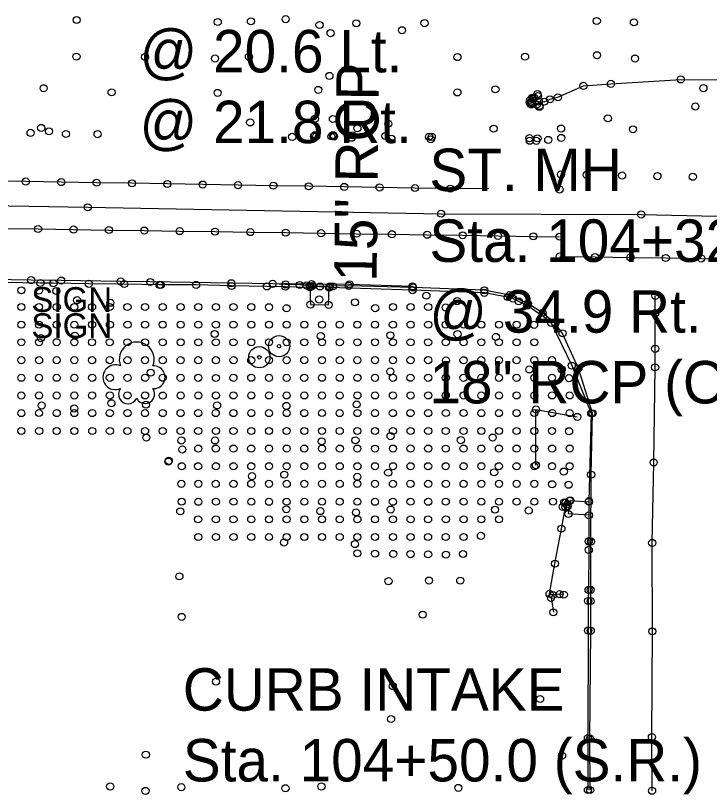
# Model space of a CAD drawing. Extents: x 20503438 to 20508873, y 7964251 to 7984667.
# Drawn here: x 20505361.4 to 20505557.5, y 7970387.9 to 7970607.9 of the extents above; entities that cross this region are included whole.
import ezdxf

# ---------------------------------------------------------------- set-up
doc = ezdxf.new("R2010")
doc.units = 0
for name, color, linetype in [('SurBreakLine', 7, 'Continuous'), ('SurBuilding', 7, 'Continuous'), ('SurConcreteSlab', 7, 'Continuous'), ('SurDrainageArrowDown', 7, 'Continuous'), ('SurDrainageArrowUp', 7, 'Continuous'), ('SurEdgeCurb', 7, 'Continuous'), ('SurEdgeRoadPaved', 7, 'Continuous'), ('SurFenceChainLink', 7, 'Continuous'), ('SurFenceWood', 7, 'Continuous'), ('SurNaturalCells', 7, 'Continuous'), ('SurPointsNonDTM', 7, 'Continuous'), ('SurRoadPoints', 7, 'Continuous'), ('SurSurveyPoints', 7, 'Continuous'), ('SurTxtDrainage', 7, 'Continuous')]:
    doc.layers.add(name, color=color, linetype=linetype)

msp = doc.modelspace()

# ---------------------------------------------------------------- linework, layer by layer
at = {"layer": 'SurBreakLine'}
for points in [[(20504771.9, 7970563.37), (20504797.86, 7970563), (20504843.99, 7970562.34), (20504867.04, 7970562.01), (20505027.11, 7970559.46), (20505056.57, 7970559.02), (20505122.33, 7970557.99), (20505134.3, 7970557.78), (20505181.34, 7970557.02), (20505190.04, 7970556.88), (20505298.19, 7970555.19), (20505381.79, 7970553.77), (20505481.65, 7970551.95), (20505538.21, 7970551.74), (20505602.69, 7970550.28), (20505659.98, 7970549.19), (20505725.91, 7970548.38)], [(20505541.3, 7970388.88), (20505541.24, 7970404.04), (20505541.37, 7970433.93), (20505541.32, 7970458.93), (20505541.74, 7970481.63), (20505542.15, 7970508.53), (20505542.17, 7970523.87), (20505542.2, 7970528.72)], [(20505517.44, 7970469.27), (20505517.44, 7970469.84), (20505516.88, 7970470.28), (20505516.46, 7970470.37), (20505516.05, 7970469.09)]]:
    msp.add_lwpolyline(points, dxfattribs=at)
at = {"layer": 'SurBuilding'}
msp.add_line((20505404.58, 7970481.91), (20505404.58, 7970481.91), dxfattribs=at)
at = {"layer": 'SurConcreteSlab'}
for points in [[(20505495.13, 7970558.96), (20505484.26, 7970559.04), (20505474.26, 7970559.2), (20505464.27, 7970559.37), (20505454.27, 7970559.53), (20505444.27, 7970559.7), (20505434.27, 7970559.86), (20505424.27, 7970560.02), (20505414.28, 7970560.19), (20505404.28, 7970560.36), (20505394.28, 7970560.54), (20505384.28, 7970560.71), (20505374.28, 7970560.88), (20505364.28, 7970561.05), (20505354.29, 7970561.22)], [(20505357.76, 7970547.78), (20505367.76, 7970547.64), (20505377.76, 7970547.49), (20505387.76, 7970547.34), (20505397.76, 7970547.19), (20505407.76, 7970547.04), (20505417.75, 7970546.89), (20505427.75, 7970546.75), (20505437.75, 7970546.6), (20505447.75, 7970546.45), (20505457.75, 7970546.3), (20505467.75, 7970546.15), (20505477.74, 7970546), (20505487.74, 7970545.86), (20505497.74, 7970545.71), (20505507.74, 7970545.56), (20505515.13, 7970545.45)], [(20505515.18, 7970539.88), (20505525.17, 7970539.73), (20505535.17, 7970539.59), (20505545.17, 7970539.44), (20505555.17, 7970539.3), (20505565.17, 7970539.15), (20505575.17, 7970539.01), (20505585.16, 7970538.86), (20505595.16, 7970538.71), (20505605.16, 7970538.57), (20505615.16, 7970538.42), (20505625.16, 7970538.27), (20505635.16, 7970538.13), (20505645.16, 7970537.98), (20505655.15, 7970537.84), (20505665.15, 7970537.69), (20505675.15, 7970537.55), (20505685.15, 7970537.4), (20505695.15, 7970537.26), (20505705.15, 7970537.12), (20505715.14, 7970537)], [(20505506.07, 7970526.04), (20505510.46, 7970522.99), (20505512.8, 7970521.08), (20505518.59, 7970509.03), (20505524.09, 7970495.56), (20505523.45, 7970470.73), (20505523.39, 7970459.44), (20505523.37, 7970459.31)]]:
    msp.add_lwpolyline(points, dxfattribs=at)
for points in [[(20505444.59, 7970531.35), (20505444.73, 7970526.28), (20505449.86, 7970526.19), (20505450.05, 7970531.21)], [(20505517.64, 7970467.11), (20505518.14, 7970470.91), (20505523.43, 7970470.56), (20505523.42, 7970466.72)]]:
    msp.add_lwpolyline(points, close=True, dxfattribs=at)
at = {"layer": 'SurDrainageArrowDown'}
msp.add_lwpolyline([(20505516.34, 7970444.31), (20505515.13, 7970444.43), (20505513.26, 7970444.21), (20505512.31, 7970444.53), (20505513.84, 7970453.07), (20505515.67, 7970462.95), (20505516.82, 7970469.04)], dxfattribs=at)
at = {"layer": 'SurDrainageArrowUp'}
for points in [[(20505509.27, 7970583.65), (20505510.79, 7970583.61), (20505512.44, 7970584.29), (20505514.65, 7970584.86), (20505521.9, 7970588.08), (20505529.65, 7970588.65), (20505549.4, 7970589.9), (20505570.14, 7970589.83)], [(20505512.72, 7970443.37), (20505513.39, 7970439.31)]]:
    msp.add_lwpolyline(points, dxfattribs=at)
at = {"layer": 'SurEdgeCurb'}
for points in [[(20505444.6, 7970531.13), (20505437.65, 7970531.33), (20505432.42, 7970531.41), (20505422.42, 7970531.53), (20505412.42, 7970531.84), (20505402.42, 7970531.84), (20505402.08, 7970531.85), (20505392.08, 7970532.07), (20505382.08, 7970532.14), (20505372.08, 7970532.28), (20505368.42, 7970532.36), (20505358.42, 7970532.5)], [(20505455.52, 7970531.57), (20505451.07, 7970531.44), (20505450.19, 7970531.38), (20505447.43, 7970531.4), (20505445.14, 7970531.49), (20505444.57, 7970531.51), (20505443.66, 7970531.66), (20505441.7, 7970531.81), (20505437.7, 7970531.96), (20505434.06, 7970532.14)], [(20505506.07, 7970526.04), (20505505.93, 7970526.03), (20505503.6, 7970527.18), (20505501.97, 7970527.96), (20505500.46, 7970528.4), (20505493.88, 7970529.59), (20505473.59, 7970530.35), (20505450.04, 7970531.07)], [(20505523.78, 7970389.08), (20505523.74, 7970403.67), (20505523.95, 7970434.1), (20505523.93, 7970442.49), (20505523.93, 7970445.66), (20505524.02, 7970459.3), (20505524.07, 7970478.22), (20505524.47, 7970495.56), (20505520.47, 7970508.23), (20505515.98, 7970518.14), (20505513.93, 7970520.95), (20505510.35, 7970523.97), (20505506.16, 7970526.54), (20505501, 7970528.93), (20505493.87, 7970530.31), (20505473.72, 7970531.12), (20505455.52, 7970531.57)], [(20505523.37, 7970459.31), (20505523.39, 7970456.96), (20505523.34, 7970445.65), (20505523.22, 7970442.53), (20505523.22, 7970434.16), (20505523.15, 7970403.79), (20505523.15, 7970389.09)]]:
    msp.add_lwpolyline(points, dxfattribs=at)
at = {"layer": 'SurEdgeRoadPaved'}
msp.add_lwpolyline([(20505473.55, 7970531.4), (20505455.77, 7970531.96), (20505445.03, 7970532.04), (20505434.06, 7970532.14), (20505422.36, 7970532.31), (20505399.47, 7970532.66), (20505391.08, 7970532.79), (20505374.29, 7970533.06), (20505365.79, 7970533.19), (20505337.25, 7970533.63), (20505320.09, 7970533.9), (20505273.98, 7970534.71), (20505259.19, 7970535), (20505244.39, 7970535.28), (20505238.48, 7970535.4)], dxfattribs=at)
at = {"layer": 'SurFenceChainLink'}
msp.add_lwpolyline([(20505508.45, 7970480.87), (20505508.47, 7970496.65), (20505520.14, 7970494.53)], dxfattribs=at)
at = {"layer": 'SurFenceWood'}
msp.add_line((20505404.68, 7970482.13), (20505404.68, 7970482.13), dxfattribs=at)
at = {"layer": 'SurNaturalCells'}
for centre, radius, start, end in [((20505395.62, 7970510.77), 4.92, 338.2051, 201.7949), ((20505389.6, 7970505.74), 3.51, 65.4824, 294.5175), ((20505400.42, 7970505.74), 3.21, 265.9982, 94.0018), ((20505393.19, 7970500.92), 2.68, 142.7501, 335.3223), ((20505398.01, 7970501), 2.67, 206.5242, 35.4033)]:
    msp.add_arc(centre, radius, start, end, dxfattribs=at)
at = {"layer": 'SurPointsNonDTM'}
for centre in [(20505525.67, 7970606.42), (20505450.41, 7970602.98), (20505470.61, 7970603.8), (20505450.1, 7970590.89), (20505542.16, 7970513.77), (20505508.47, 7970496.65), (20505520.14, 7970494.53), (20505404.58, 7970481.91), (20505404.68, 7970482.13), (20505508.45, 7970480.87)]:
    msp.add_circle(centre, 1, dxfattribs=at)
at = {"layer": 'SurRoadPoints'}
for centre, radius in [((20505435.86, 7970514.52), 3), ((20505430.27, 7970511.39), 3), ((20505435.86, 7970514.52), 0.5), ((20505430.27, 7970511.39), 0.5)]:
    msp.add_circle(centre, radius, dxfattribs=at)
at = {"layer": 'SurSurveyPoints'}
for centre in [(20505378.64, 7970606.69), (20505437.73, 7970606.94), (20505418.53, 7970606.12), (20505427.9, 7970606.32), (20505447.29, 7970605.29), (20505457.7, 7970605.76), (20505476.97, 7970605.8), (20505536.15, 7970606.02), (20505378.6, 7970596.35), (20505397.97, 7970596.25), (20505417.76, 7970595.81), (20505427.33, 7970596.31), (20505486.27, 7970596.21), (20505505.4, 7970596.32), (20505525.73, 7970596.73), (20505536.46, 7970595.8), (20505549.4, 7970589.9), (20505369.31, 7970587.41), (20505446.94, 7970586.94), (20505497.02, 7970587.1), (20505521.9, 7970588.08), (20505529.65, 7970588.65), (20505555.8, 7970587.43), (20505388.52, 7970586.25), (20505418.49, 7970586.1), (20505486.27, 7970586.23), (20505507.44, 7970584.76), (20505507.98, 7970584.71), (20505508.88, 7970585.76), (20505509.02, 7970585.22), (20505514.65, 7970584.86), (20505506.74, 7970583.37), (20505506.83, 7970584.11), (20505507.07, 7970583.6), (20505507.09, 7970582.84), (20505507.38, 7970583.19), (20505507.5, 7970584.39), (20505508.69, 7970582.76), (20505509.27, 7970583.65), (20505509.48, 7970582.37), (20505510.79, 7970583.61), (20505512.44, 7970584.29), (20505509.45, 7970582.12), (20505553.53, 7970582.26), (20505445.99, 7970578.81), (20505451.08, 7970578.72), (20505528.79, 7970578.89), (20505368.62, 7970576.21), (20505427.7, 7970577.74), (20505458, 7970576.1), (20505466.74, 7970577.38), (20505496.49, 7970575.98), (20505515.58, 7970576.01), (20505515.58, 7970576.01), (20505535.9, 7970575.81), (20505365.62, 7970574.8), (20505370.84, 7970575.22), (20505375.61, 7970574.47), (20505384.56, 7970574.44), (20505439.56, 7970573.67), (20505445.77, 7970573.81), (20505445.98, 7970574.14), (20505445.98, 7970574.04), (20505446.4, 7970573.88), (20505450.65, 7970573.8), (20505451.09, 7970574.21), (20505451.09, 7970573.91), (20505451.4, 7970573.77), (20505455.28, 7970574.06), (20505456.57, 7970574.12), (20505465.9, 7970573.92), (20505478.27, 7970573.68), (20505479.02, 7970573.68), (20505456.35, 7970573.41), (20505467.61, 7970573.12), (20505478.75, 7970572.99), (20505506.63, 7970573.3), (20505506.7, 7970572.57), (20505508.57, 7970572.54), (20505508.9, 7970573.26), (20505511.94, 7970572.81), (20505515.61, 7970573.37), (20505515.54, 7970563.06), (20505522.81, 7970562.93), (20505532.81, 7970562.75), (20505542.8, 7970562.57), (20505364.28, 7970561.05), (20505374.28, 7970560.88), (20505384.28, 7970560.71), (20505394.28, 7970560.54), (20505404.28, 7970560.36), (20505552.8, 7970562.39), (20505414.28, 7970560.19), (20505424.27, 7970560.02), (20505434.27, 7970559.86), (20505444.27, 7970559.7), (20505454.27, 7970559.53), (20505464.27, 7970559.37), (20505474.26, 7970559.2), (20505484.26, 7970559.04), (20505515.12, 7970558.8), (20505381.79, 7970553.77), (20505481.65, 7970551.95), (20505538.21, 7970551.74), (20505367.76, 7970547.64), (20505377.76, 7970547.49), (20505387.76, 7970547.34), (20505397.76, 7970547.19), (20505407.76, 7970547.04), (20505417.75, 7970546.89), (20505427.75, 7970546.75), (20505437.75, 7970546.6), (20505447.75, 7970546.45), (20505457.75, 7970546.3), (20505467.75, 7970546.15), (20505477.74, 7970546), (20505487.74, 7970545.86), (20505497.74, 7970545.71), (20505507.74, 7970545.56), (20505515.13, 7970545.45), (20505515.18, 7970539.88), (20505525.17, 7970539.73), (20505535.17, 7970539.59), (20505545.17, 7970539.44), (20505555.17, 7970539.3), (20505365.79, 7970533.19), (20505368.42, 7970532.36), (20505372.08, 7970532.28), (20505374.29, 7970533.06), (20505382.08, 7970532.14), (20505391.08, 7970532.79), (20505392.08, 7970532.07), (20505399.47, 7970532.66), (20505402.08, 7970531.85), (20505402.42, 7970531.84), (20505412.42, 7970531.84), (20505422.36, 7970532.31), (20505434.06, 7970532.14), (20505437.7, 7970531.96), (20505441.7, 7970531.81), (20505445.03, 7970532.04), (20505455.77, 7970531.96), (20505363.01, 7970530.31), (20505367.97, 7970530.22), (20505372.89, 7970530.11), (20505422.42, 7970531.53), (20505432.42, 7970531.41), (20505437.65, 7970531.33), (20505443.66, 7970531.66), (20505444.57, 7970531.51), (20505444.59, 7970531.35), (20505444.6, 7970531.13), (20505445.14, 7970531.49), (20505447.43, 7970531.4), (20505450.05, 7970531.21), (20505450.04, 7970531.07), (20505450.19, 7970531.38), (20505451.07, 7970531.44), (20505455.52, 7970531.57), (20505455.52, 7970531.57), (20505473.55, 7970531.4), (20505473.59, 7970530.35), (20505473.72, 7970531.12), (20505493.87, 7970530.31), (20505493.88, 7970529.59), (20505378.78, 7970527.52), (20505447.2, 7970527.71), (20505477.51, 7970528.79), (20505500.46, 7970528.4), (20505501, 7970528.93), (20505501.97, 7970527.96), (20505542.2, 7970528.72), (20505363, 7970525.6), (20505368.02, 7970525.59), (20505373.02, 7970525.59), (20505377.99, 7970525.59), (20505383.01, 7970525.6), (20505388.02, 7970525.58), (20505388.16, 7970526.78), (20505393.01, 7970525.59), (20505398, 7970525.58), (20505402.98, 7970525.58), (20505408.02, 7970525.59), (20505413.01, 7970525.59), (20505418, 7970525.59), (20505422.97, 7970525.59), (20505427.99, 7970525.59), (20505433, 7970525.52), (20505437.98, 7970525.24), (20505444.73, 7970526.28), (20505449.86, 7970526.19), (20505457.34, 7970526.9), (20505463.02, 7970525.27), (20505468.04, 7970525.58), (20505473.02, 7970525.58), (20505478.01, 7970525.59), (20505482.95, 7970525.47), (20505486.22, 7970527.24), (20505503.6, 7970527.18), (20505505.93, 7970526.03), (20505506.07, 7970526.04), (20505506.16, 7970526.54), (20505510.35, 7970523.97), (20505510.46, 7970522.99), (20505542.17, 7970523.87), (20505512.8, 7970521.08), (20505513.93, 7970520.95), (20505363, 7970520.59), (20505368.02, 7970520.6), (20505373.01, 7970520.6), (20505377.98, 7970520.58), (20505383.01, 7970520.6), (20505388.04, 7970520.61), (20505393.02, 7970520.59), (20505397.99, 7970520.6), (20505402.97, 7970520.61), (20505408.03, 7970520.6), (20505413.01, 7970520.6), (20505417.99, 7970520.6), (20505422.97, 7970520.6), (20505428, 7970520.6), (20505433.01, 7970520.6), (20505438, 7970520.6), (20505442.99, 7970520.6), (20505448.01, 7970520.61), (20505453.01, 7970520.61), (20505457.99, 7970520.6), (20505462.98, 7970520.6), (20505468.02, 7970520.6), (20505473.03, 7970520.6), (20505478, 7970520.6), (20505482.98, 7970520.61), (20505488, 7970520.59), (20505493.02, 7970520.6), (20505498, 7970520.6), (20505503, 7970520.6), (20505507.94, 7970520.56), (20505368.54, 7970516.79), (20505378.15, 7970517.46), (20505417.65, 7970517.96), (20505447.66, 7970517.35), (20505467.29, 7970517.59), (20505486.3, 7970517.92), (20505497.15, 7970517.14), (20505515.98, 7970518.14), (20505363, 7970515.62), (20505368.02, 7970515.62), (20505373.01, 7970515.63), (20505377.99, 7970515.62), (20505383, 7970515.61), (20505388.01, 7970515.62), (20505393.01, 7970515.61), (20505397.99, 7970515.62), (20505402.99, 7970515.62), (20505408.04, 7970515.61), (20505413.01, 7970515.61), (20505417.99, 7970515.62), (20505422.97, 7970515.61), (20505427.99, 7970515.62), (20505433.01, 7970515.62), (20505438.01, 7970515.62), (20505442.97, 7970515.61), (20505448, 7970515.62), (20505453.03, 7970515.61), (20505458.01, 7970515.62), (20505462.98, 7970515.62), (20505468.03, 7970515.62), (20505473.01, 7970515.61), (20505477.99, 7970515.62), (20505482.99, 7970515.62), (20505488, 7970515.61), (20505493.02, 7970515.62), (20505497.98, 7970515.62), (20505502.98, 7970515.61), (20505508.01, 7970515.61), (20505363.01, 7970510.56), (20505368.03, 7970510.56), (20505373.01, 7970510.57), (20505377.99, 7970510.56), (20505383.02, 7970510.56), (20505388.01, 7970510.57), (20505393.02, 7970510.56), (20505397.98, 7970510.56), (20505402.98, 7970510.56), (20505408.02, 7970510.56), (20505413.01, 7970510.56), (20505418, 7970510.56), (20505422.98, 7970510.56), (20505427.99, 7970510.56), (20505433.02, 7970510.56), (20505438, 7970510.56), (20505442.97, 7970510.57), (20505448.01, 7970510.55), (20505453.03, 7970510.56), (20505457.99, 7970510.57), (20505462.98, 7970510.56), (20505468.04, 7970510.56), (20505473.01, 7970510.56), (20505478, 7970510.57), (20505483.03, 7970510.48), (20505487.99, 7970510.55), (20505493, 7970510.56), (20505498.02, 7970510.56), (20505502.98, 7970510.56), (20505508, 7970510.56), (20505513.01, 7970510.56), (20505506.6, 7970507.95), (20505515.76, 7970507.93), (20505518.59, 7970509.03), (20505520.47, 7970508.23), (20505542.15, 7970508.53), (20505363.01, 7970505.59), (20505368.02, 7970505.58), (20505373, 7970505.6), (20505377.98, 7970505.58), (20505383.04, 7970505.58), (20505388.03, 7970505.58), (20505393.02, 7970505.58), (20505398.01, 7970505.59), (20505399.55, 7970507.03), (20505402.99, 7970505.59), (20505408.01, 7970505.58), (20505413.01, 7970505.58), (20505418, 7970505.54), (20505422.96, 7970505.58), (20505427.99, 7970505.59), (20505433.01, 7970505.58), (20505438.01, 7970505.58), (20505442.96, 7970505.58), (20505448, 7970505.59), (20505453.01, 7970505.59), (20505458.01, 7970505.59), (20505462.98, 7970505.58), (20505467.3, 7970507.39), (20505468.03, 7970505.58), (20505473, 7970505.59), (20505478, 7970505.58), (20505482.99, 7970505.59), (20505487.99, 7970505.58), (20505493.01, 7970505.58), (20505498, 7970505.58), (20505502.99, 7970505.58), (20505508, 7970505.57), (20505513.01, 7970505.59), (20505517.8, 7970505.48), (20505363, 7970500.59), (20505368.01, 7970500.6), (20505373, 7970500.58), (20505377.98, 7970500.58), (20505383.02, 7970500.59), (20505388.03, 7970500.59), (20505393.01, 7970500.6), (20505397.99, 7970500.6), (20505402.98, 7970500.56), (20505408.04, 7970500.6), (20505413.03, 7970500.6), (20505418, 7970500.6), (20505422.97, 7970500.6), (20505428, 7970500.6), (20505433.01, 7970500.6), (20505437.99, 7970500.6), (20505442.99, 7970500.6), (20505448, 7970500.59), (20505453, 7970500.6), (20505458.01, 7970500.6), (20505462.99, 7970500.6), (20505468.03, 7970500.59), (20505473.02, 7970500.59), (20505478.01, 7970500.6), (20505482.97, 7970500.59), (20505488.01, 7970500.59), (20505493.03, 7970500.6), (20505498.01, 7970500.6), (20505502.99, 7970500.6), (20505508, 7970500.59), (20505513.03, 7970500.6), (20505518.01, 7970500.6), (20505368.76, 7970497.75), (20505377.97, 7970496.91), (20505388.47, 7970498.4), (20505398.25, 7970497.99), (20505418.34, 7970497.78), (20505437.94, 7970497.64), (20505457.78, 7970498.07), (20505363, 7970495.61), (20505368, 7970495.62), (20505373.02, 7970495.61), (20505377.98, 7970495.61), (20505383.04, 7970495.61), (20505388.02, 7970495.61), (20505393.02, 7970495.61), (20505397.97, 7970495.61), (20505402.98, 7970495.61), (20505408.02, 7970495.61), (20505413, 7970495.61), (20505417.97, 7970495.61), (20505422.96, 7970495.61), (20505428, 7970495.61), (20505433.01, 7970495.61), (20505438.02, 7970495.61), (20505442.97, 7970495.61), (20505447.99, 7970495.62), (20505452.99, 7970495.61), (20505458, 7970495.61), (20505462.98, 7970495.61), (20505468.02, 7970495.61), (20505473, 7970495.61), (20505478, 7970495.61), (20505483, 7970495.62), (20505488, 7970495.62), (20505493.02, 7970495.61), (20505498, 7970495.61), (20505502.98, 7970495.61), (20505508, 7970495.62), (20505513.06, 7970495.61), (20505518.01, 7970495.61), (20505524.09, 7970495.56), (20505524.47, 7970495.56), (20505363.01, 7970490.56), (20505368.06, 7970490.56), (20505373, 7970490.56), (20505377.99, 7970490.56), (20505383.05, 7970490.56), (20505388.03, 7970490.56), (20505393, 7970490.56), (20505397.99, 7970490.55), (20505402.99, 7970490.56), (20505408.02, 7970490.55), (20505413, 7970490.55), (20505418, 7970490.56), (20505422.97, 7970490.56), (20505427.99, 7970490.56), (20505433.02, 7970490.56), (20505437.98, 7970490.57), (20505442.98, 7970490.56), (20505448, 7970490.57), (20505453.01, 7970490.55), (20505457.99, 7970490.56), (20505462.99, 7970490.56), (20505468.03, 7970490.55), (20505473.02, 7970490.54), (20505478, 7970490.56), (20505482.98, 7970490.54), (20505488, 7970490.56), (20505493.02, 7970490.56), (20505498, 7970490.56), (20505502.99, 7970490.55), (20505508.01, 7970490.56), (20505513.01, 7970490.57), (20505517.83, 7970490.49), (20505398.33, 7970488.68), (20505408.26, 7970487.87), (20505417.76, 7970487.88), (20505457.46, 7970487.92), (20505467.37, 7970489.1), (20505487.24, 7970487.97), (20505496.23, 7970488.69), (20505413.01, 7970485.59), (20505417.98, 7970485.58), (20505422.97, 7970485.58), (20505427.98, 7970485.58), (20505433.01, 7970485.58), (20505438.01, 7970485.58), (20505442.97, 7970485.58), (20505447.88, 7970487.62), (20505448, 7970485.59), (20505453.04, 7970485.58), (20505457.99, 7970485.58), (20505462.97, 7970485.57), (20505468.04, 7970485.59), (20505473.01, 7970485.6), (20505478, 7970485.58), (20505482.98, 7970485.57), (20505487.99, 7970485.59), (20505493.03, 7970485.58), (20505497.99, 7970485.58), (20505502.99, 7970485.59), (20505508.01, 7970485.58), (20505513.03, 7970485.58), (20505518, 7970485.58), (20505408.5, 7970485.33), (20505541.74, 7970481.63), (20505408.36, 7970480.6), (20505412.99, 7970480.6), (20505418, 7970480.6), (20505422.97, 7970480.6), (20505427.99, 7970480.59), (20505433.02, 7970480.6), (20505438, 7970480.6), (20505442.98, 7970480.6), (20505448, 7970480.6), (20505453.02, 7970480.6), (20505458.01, 7970480.59), (20505462.98, 7970480.6), (20505468.05, 7970480.59), (20505473.02, 7970480.59), (20505477.99, 7970480.6), (20505482.96, 7970480.59), (20505488.01, 7970480.59), (20505493.02, 7970480.59), (20505497.97, 7970480.59), (20505502.97, 7970480.6), (20505508.02, 7970480.61), (20505513.02, 7970480.59), (20505516.34, 7970479.08), (20505518, 7970480.6), (20505428.21, 7970477.79), (20505437.32, 7970478.23), (20505457.97, 7970477.61), (20505466.7, 7970478.78), (20505496.65, 7970478.88), (20505524.07, 7970478.22), (20505408.24, 7970475.61), (20505413.03, 7970475.61), (20505417.96, 7970475.61), (20505422.98, 7970475.61), (20505427.99, 7970475.62), (20505433.01, 7970475.61), (20505438.03, 7970475.61), (20505442.98, 7970475.61), (20505448, 7970475.61), (20505453.01, 7970475.61), (20505457.97, 7970475.61), (20505462.97, 7970475.61), (20505468.03, 7970475.61), (20505473, 7970475.62), (20505478, 7970475.61), (20505483, 7970475.62), (20505488, 7970475.61), (20505493.04, 7970475.61), (20505498.02, 7970475.61), (20505503.01, 7970475.61), (20505508, 7970475.61), (20505513.04, 7970475.5), (20505517.68, 7970475.36), (20505408.33, 7970470.58), (20505413.03, 7970470.55), (20505418, 7970470.56), (20505422.98, 7970470.56), (20505428.01, 7970470.56), (20505433, 7970470.55), (20505437.97, 7970470.56), (20505442.98, 7970470.56), (20505448, 7970470.56), (20505453.02, 7970470.56), (20505457.99, 7970470.56), (20505462.98, 7970470.55), (20505468.02, 7970470.55), (20505473.01, 7970470.56), (20505478, 7970470.55), (20505482.97, 7970470.56), (20505488, 7970470.56), (20505493.03, 7970470.56), (20505498, 7970470.56), (20505502.99, 7970470.56), (20505508, 7970470.56), (20505513.29, 7970470.59), (20505516.46, 7970470.37), (20505516.88, 7970470.28), (20505517.95, 7970470.85), (20505518.14, 7970470.91), (20505523.43, 7970470.56), (20505523.45, 7970470.73), (20505437.92, 7970468.43), (20505447.51, 7970467.91), (20505467.4, 7970468.35), (20505496.87, 7970468.31), (20505506.44, 7970468.08), (20505516.05, 7970469.09), (20505516.82, 7970469.04), (20505517.44, 7970469.84), (20505517.44, 7970469.27), (20505407.93, 7970467.85), (20505457.62, 7970467.54), (20505517.64, 7970467.11), (20505523.42, 7970466.72), (20505412.99, 7970465.58), (20505417.99, 7970465.58), (20505422.97, 7970465.58), (20505427.99, 7970465.57), (20505433, 7970465.58), (20505437.97, 7970465.58), (20505442.98, 7970465.58), (20505448, 7970465.58), (20505453.02, 7970465.58), (20505458.01, 7970465.57), (20505462.97, 7970465.58), (20505468.03, 7970465.58), (20505473.03, 7970465.58), (20505477.98, 7970465.58), (20505483, 7970465.59), (20505488, 7970465.59), (20505493.04, 7970465.58), (20505498, 7970465.58), (20505515.67, 7970462.95), (20505413.01, 7970460.59), (20505418, 7970460.6), (20505422.98, 7970460.59), (20505427.98, 7970460.6), (20505433.01, 7970460.58), (20505438.01, 7970460.59), (20505443, 7970460.59), (20505448, 7970460.59), (20505453.02, 7970460.59), (20505457.99, 7970460.59), (20505462.99, 7970460.59), (20505468.04, 7970460.6), (20505473.03, 7970460.6), (20505477.98, 7970460.59), (20505482.98, 7970460.6), (20505488, 7970460.59), (20505492.91, 7970460.92), (20505523.37, 7970459.31), (20505523.39, 7970459.44), (20505524.02, 7970459.3), (20505437.28, 7970459.05), (20505457.29, 7970458.59), (20505523.39, 7970456.96), (20505541.32, 7970458.93), (20505457.96, 7970455.98), (20505463, 7970455.9), (20505468.12, 7970455.82), (20505473.01, 7970455.75), (20505477.99, 7970455.68), (20505483.01, 7970455.62), (20505487.84, 7970455.8), (20505513.84, 7970453.07), (20505407.69, 7970449.46), (20505466.78, 7970448.11), (20505478.24, 7970448.29), (20505487.07, 7970448.27), (20505512.31, 7970444.53), (20505513.26, 7970444.21), (20505515.13, 7970444.43), (20505516.34, 7970444.31), (20505523.34, 7970445.65), (20505523.93, 7970445.66), (20505512.72, 7970443.37), (20505523.22, 7970442.53), (20505523.93, 7970442.49), (20505513.39, 7970439.31), (20505408.33, 7970438.02), (20505476.45, 7970438.66), (20505523.22, 7970434.16), (20505523.95, 7970434.1), (20505541.37, 7970433.93), (20505418.04, 7970419.72), (20505467.99, 7970418.45), (20505509.64, 7970414.81), (20505467.53, 7970409.15), (20505523.15, 7970403.79), (20505523.74, 7970403.67), (20505541.24, 7970404.04), (20505398.2, 7970399.08), (20505515.86, 7970398.8), (20505388.13, 7970390.09), (20505398.1, 7970388.85), (20505408.23, 7970389.91), (20505437.67, 7970389.6), (20505447.85, 7970390.09), (20505486.51, 7970389.7), (20505523.15, 7970389.09), (20505523.78, 7970389.08), (20505541.3, 7970388.88)]:
    msp.add_circle(centre, 1, dxfattribs=at)

# ---------------------------------------------------------------- texts
at = {"layer": 'SurRoadPoints'}
for p in [(20505365.82, 7970524.2), (20505365.84, 7970516.8)]:
    msp.add_text('SIGN', height=6.995, rotation=360, dxfattribs=at).set_placement(p)
at = {"layer": 'SurTxtDrainage'}
for s, p in [('@ 20.6 Lt.', (20505396.44, 7970591.89)), ('@ 21.8 Rt.', (20505396.44, 7970571.89)), ('ST. MH', (20505478.35, 7970558.34)), ('Sta. 104+32.1 (S.R.)', (20505478.35, 7970538.34)), ('@ 34.9 Rt.', (20505478.35, 7970518.34)), ('18" RCP (Out) to W./NW.', (20505478.35, 7970498.34)), ('CURB INTAKE', (20505408.65, 7970411.52)), ('Sta. 104+50.0 (S.R.)', (20505408.65, 7970391.52))]:
    msp.add_text(s, height=12, dxfattribs=at).set_placement(p)
msp.add_text('15" RCP', height=12, rotation=89.3392, dxfattribs=at).set_placement((20505463.41, 7970532.68))

doc.saveas('drawing.dxf')
